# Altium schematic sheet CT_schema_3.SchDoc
size 283 x 147 mm
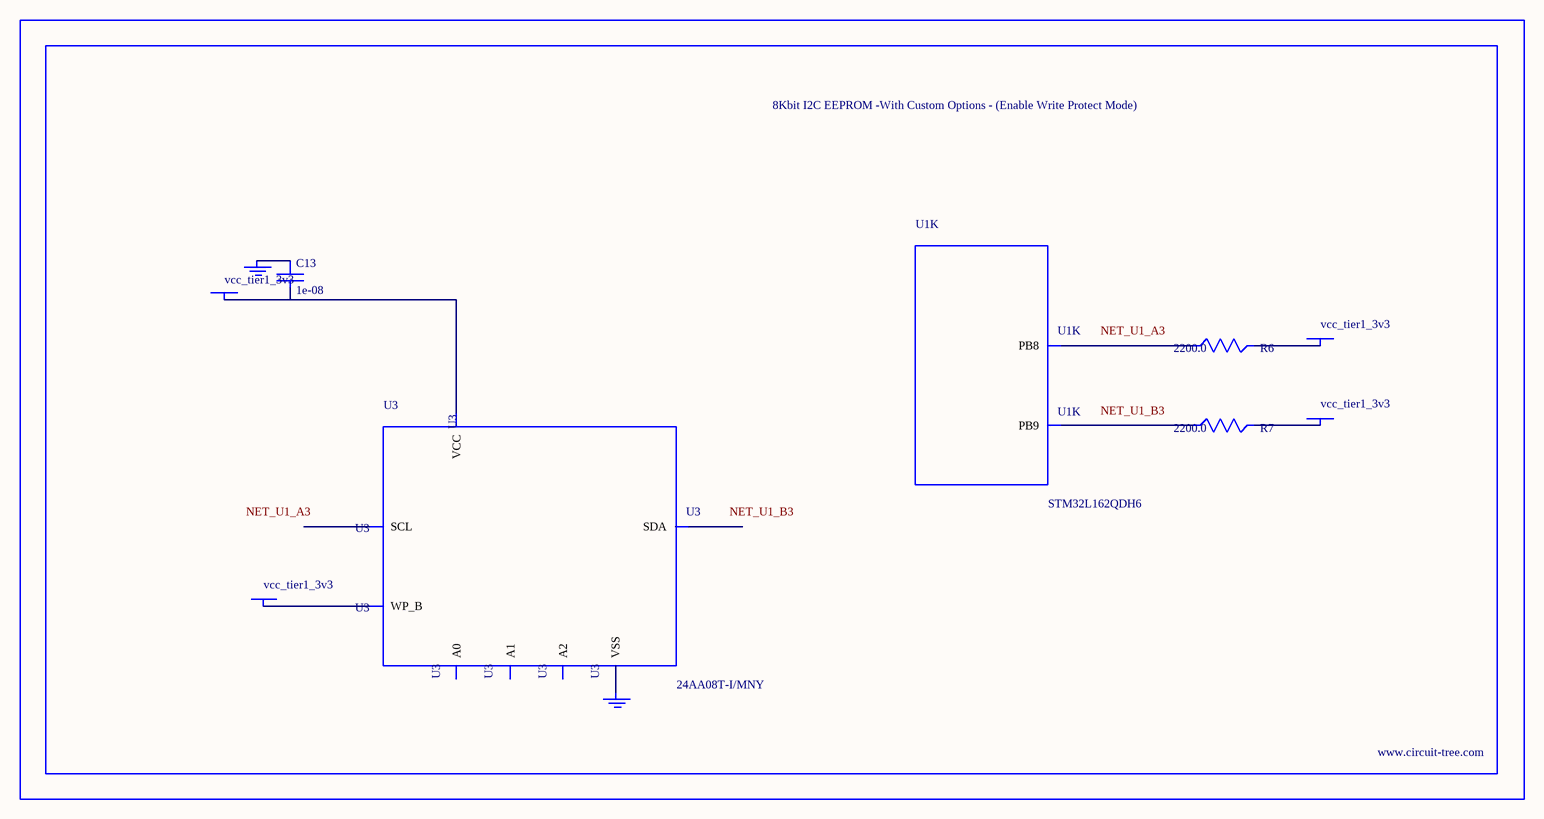
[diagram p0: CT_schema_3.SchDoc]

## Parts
BORDER2  (no value)
C13  1e-08  [C0402]
GND_INSTANCE_2_0  (no value)
GND_INSTANCE_2_1  (no value)
POWER_INSTANCE_2_0  vcc_tier1_3v3
POWER_INSTANCE_2_1  vcc_tier1_3v3
POWER_INSTANCE_2_2  vcc_tier1_3v3
POWER_INSTANCE_2_3  vcc_tier1_3v3
R6  2200.0  [R0603]
R7  2200.0  [R0603]
U1  STM32L162QDH6  [UFBGA132]  (part K of 12)
U3  24AA08T-I/MNY  [TDFN-8/6MM]

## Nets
NetC13_1: C13.1 GND_INSTANCE_2_0.0(GND)
NetC13_2: C13.2 POWER_INSTANCE_2_1.0(PWR) U3.8(VCC)
NetGND_INSTANCE_2_1_0: GND_INSTANCE_2_1.0(GND) U3.4(VSS)
NetPOWER_INSTANCE_2_0_0: POWER_INSTANCE_2_0.0(PWR) U3.7(WP_B)
NetPOWER_INSTANCE_2_2_0: POWER_INSTANCE_2_2.0(PWR) R6.2
NetPOWER_INSTANCE_2_3_0: POWER_INSTANCE_2_3.0(PWR) R7.2
NetR6_1: R6.1 U1.A3(PB8)
NetR7_1: R7.1 U1.B3(PB9)

Not connected (* = marked no-connect by the designer): U3 1(A0) 2(A1) 3(A2) 5(SDA) 6(SCL)

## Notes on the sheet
- Labels drawn without touching a wire or pin: NET_U1_A3, NET_U1_B3

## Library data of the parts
BORDER2 = BORDER_PAGE2
C13 = C0402C103K3RAC
GND_INSTANCE_2_0 GND_INSTANCE_2_1 = GND
POWER_INSTANCE_2_0-POWER_INSTANCE_2_3 = PWR
R6 R7 = RC0603JR-072K2L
